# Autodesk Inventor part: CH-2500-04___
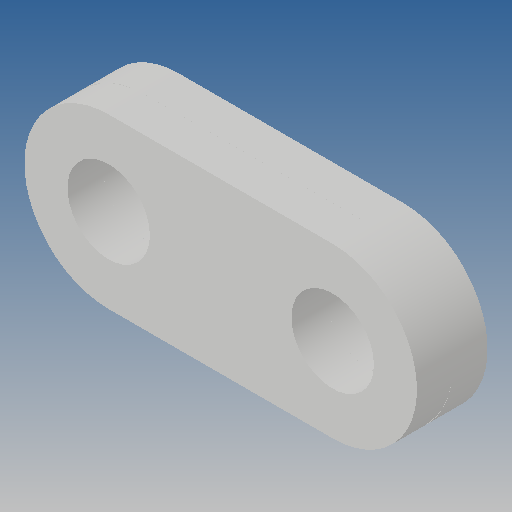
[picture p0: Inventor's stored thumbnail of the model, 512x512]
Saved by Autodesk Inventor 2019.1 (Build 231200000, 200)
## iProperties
Created: 2012-09
Part Number: CH-2500-04___
Material: Ogólny
Document SubType Name: Modeling
Designer: CADENGINEERING4
Density: 1 g/cm^3
Appearance: Domyślna
Author: CADENGINEERING4
Revision Number: ÈÎºÎ
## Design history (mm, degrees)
feature "NONE" [ÊäÈë]
feature "ÊäÈë2"
node "Bryła1"
node "Bryła2"
